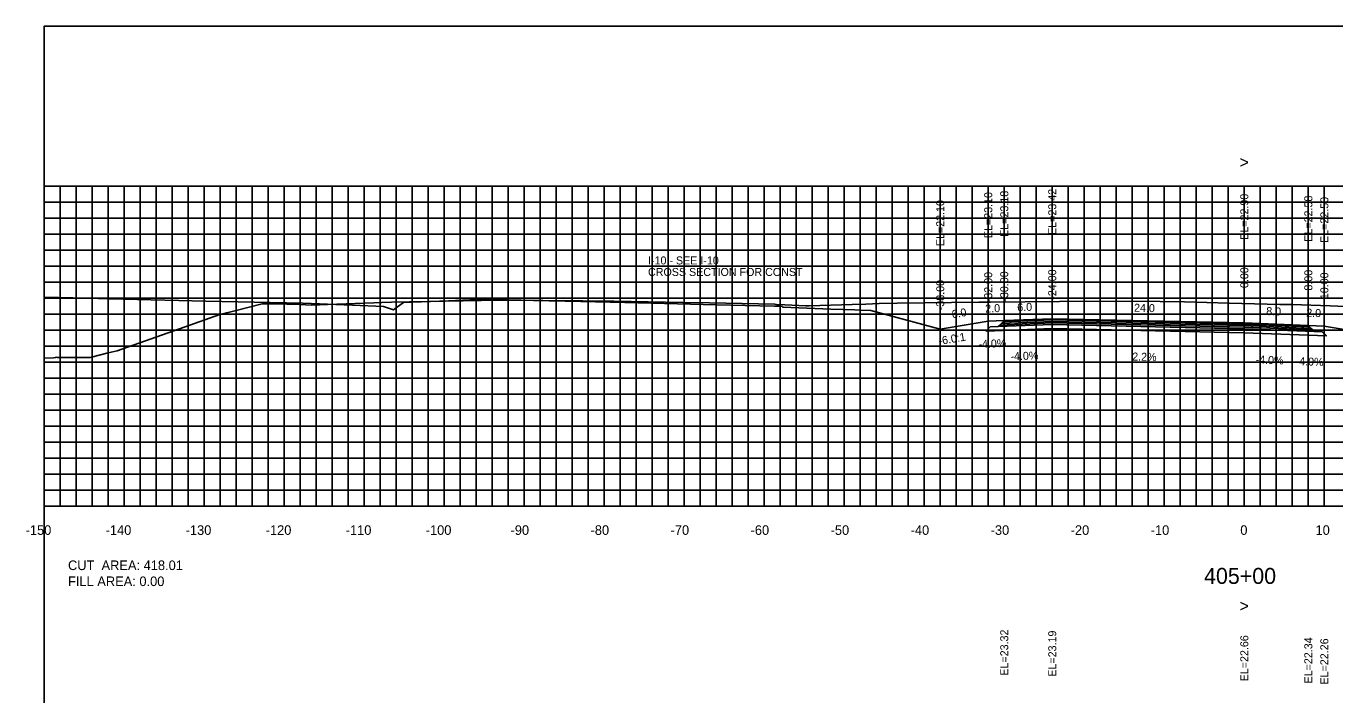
# Model space of a CAD drawing. Extents: x 1800976 to 1805104, y 250057 to 250580.
# Drawn here: x 1802478.8 to 1802642.3, y 250185.8 to 250269.4 of the extents above; entities that cross this region are included whole.
import ezdxf

# ---------------------------------------------------------------- set-up
doc = ezdxf.new("R2010")
doc.units = 0
for name, color, linetype in [('1', 7, 'Continuous'), ('10', 7, 'Continuous'), ('3', 7, 'Continuous'), ('4', 7, 'Continuous'), ('60', 7, 'Continuous'), ('ANNO-TXT', 7, 'Continuous'), ('BASE', 7, 'Continuous'), ('CL-CNST', 7, 'Continuous'), ('Level 62', 7, 'Continuous'), ('LOWER BINDER', 7, 'Continuous'), ('M-ROADS', 7, 'Continuous'), ('UPPER BINDER', 7, 'Continuous'), ('WEARING', 7, 'Continuous')]:
    doc.layers.add(name, color=color, linetype=linetype)

msp = doc.modelspace()

# ---------------------------------------------------------------- linework, layer by layer
for p, q in [((1802607, 250232.86), (1802607, 250234.86)), ((1802593, 250231.54), (1802593, 250233.54)), ((1802599, 250232.54), (1802599, 250234.54)), ((1802601, 250232.62), (1802601, 250234.62)), ((1802631, 250232.33), (1802631, 250234.33)), ((1802639, 250232.01), (1802639, 250234.01)), ((1802641, 250231.93), (1802641, 250233.93))]:
    msp.add_line(p, q)
msp.add_lwpolyline([(1802481, 250079.43), (1802781, 250079.43), (1802781, 250269.43), (1802481, 250269.43)], close=True)
at = {"layer": '60'}
for p, q in [((1802480.94, 250249.43), (1802481, 250249.43)), ((1802481, 250209.43), (1802481, 250249.43)), ((1802480.94, 250239.43), (1802481, 250239.43)), ((1802480.94, 250229.43), (1802481, 250229.43)), ((1802480.94, 250219.43), (1802481, 250219.43)), ((1802480.94, 250209.43), (1802481, 250209.43)), ((1802481, 250209.43), (1802781, 250209.43)), ((1802481, 250209.37), (1802481, 250209.43)), ((1802491, 250209.37), (1802491, 250209.43)), ((1802501, 250209.37), (1802501, 250209.43)), ((1802511, 250209.37), (1802511, 250209.43)), ((1802521, 250209.37), (1802521, 250209.43)), ((1802531, 250209.37), (1802531, 250209.43)), ((1802541, 250209.37), (1802541, 250209.43)), ((1802551, 250209.37), (1802551, 250209.43)), ((1802561, 250209.37), (1802561, 250209.43)), ((1802571, 250209.37), (1802571, 250209.43)), ((1802581, 250209.37), (1802581, 250209.43)), ((1802591, 250209.37), (1802591, 250209.43)), ((1802601, 250209.37), (1802601, 250209.43)), ((1802611, 250209.37), (1802611, 250209.43)), ((1802621, 250209.37), (1802621, 250209.43)), ((1802631, 250209.37), (1802631, 250209.43)), ((1802641, 250209.37), (1802641, 250209.43))]:
    msp.add_line(p, q, dxfattribs=at)
at = {"layer": 'BASE'}
msp.add_lwpolyline([(1802599.25, 250231.83), (1802600.25, 250231.87), (1802607, 250232.14), (1802631, 250231.61), (1802639.75, 250231.26), (1802640.75, 250231.22), (1802641.27, 250230.7), (1802631, 250231.11), (1802607, 250231.64), (1802598.73, 250231.3)], close=True, dxfattribs=at)
at = {"layer": 'CL-CNST'}
for points in [[(1802481, 250235.54), (1802486.39, 250235.41), (1802489.16, 250235.35), (1802497.83, 250235.15), (1802501.24, 250235.07), (1802509.28, 250234.88), (1802513.33, 250234.78), (1802519.54, 250234.53), (1802523.41, 250234.37), (1802523.92, 250234.21), (1802524.66, 250233.98), (1802525.18, 250234.35), (1802525.92, 250234.89), (1802531.56, 250235.11), (1802535.99, 250235.28), (1802542.15, 250235.14), (1802548.08, 250235), (1802553.58, 250234.87), (1802560.16, 250234.72), (1802565.01, 250234.6), (1802572.25, 250234.44), (1802572.89, 250234.41), (1802573.25, 250234.39), (1802573.28, 250234.37), (1802573.32, 250234.32), (1802579.33, 250234.07), (1802582.32, 250233.95), (1802582.95, 250233.92), (1802584.33, 250233.87), (1802593, 250231.54)], [(1802593, 250231.54), (1802599, 250232.54), (1802601, 250232.62), (1802607, 250232.86), (1802631, 250232.33), (1802639, 250232.01), (1802641, 250231.93), (1802671, 250226.93), (1802675, 250226.93), (1802697.32, 250232.51)]]:
    msp.add_lwpolyline(points, dxfattribs=at)
at = {"layer": 'Level 62'}
for p, q in [((1802481, 250249.43), (1802781, 250249.43)), ((1802481, 250209.43), (1802481, 250249.43)), ((1802483, 250209.43), (1802483, 250249.43)), ((1802485, 250209.43), (1802485, 250249.43)), ((1802487, 250209.43), (1802487, 250249.43)), ((1802489, 250209.43), (1802489, 250249.43)), ((1802491, 250209.43), (1802491, 250249.43)), ((1802493, 250209.43), (1802493, 250249.43)), ((1802495, 250209.43), (1802495, 250249.43)), ((1802497, 250209.43), (1802497, 250249.43)), ((1802499, 250209.43), (1802499, 250249.43)), ((1802501, 250209.43), (1802501, 250249.43)), ((1802503, 250209.43), (1802503, 250249.43)), ((1802505, 250209.43), (1802505, 250249.43)), ((1802507, 250209.43), (1802507, 250249.43)), ((1802509, 250209.43), (1802509, 250249.43)), ((1802511, 250209.43), (1802511, 250249.43)), ((1802513, 250209.43), (1802513, 250249.43)), ((1802515, 250209.43), (1802515, 250249.43)), ((1802517, 250209.43), (1802517, 250249.43)), ((1802519, 250209.43), (1802519, 250249.43)), ((1802521, 250209.43), (1802521, 250249.43)), ((1802523, 250209.43), (1802523, 250249.43)), ((1802525, 250209.43), (1802525, 250249.43)), ((1802527, 250209.43), (1802527, 250249.43)), ((1802529, 250209.43), (1802529, 250249.43)), ((1802531, 250209.43), (1802531, 250249.43)), ((1802533, 250209.43), (1802533, 250249.43)), ((1802535, 250209.43), (1802535, 250249.43)), ((1802537, 250209.43), (1802537, 250249.43)), ((1802539, 250209.43), (1802539, 250249.43)), ((1802541, 250209.43), (1802541, 250249.43)), ((1802543, 250209.43), (1802543, 250249.43)), ((1802545, 250209.43), (1802545, 250249.43)), ((1802547, 250209.43), (1802547, 250249.43)), ((1802549, 250209.43), (1802549, 250249.43)), ((1802551, 250209.43), (1802551, 250249.43)), ((1802553, 250209.43), (1802553, 250249.43)), ((1802555, 250209.43), (1802555, 250249.43)), ((1802557, 250209.43), (1802557, 250249.43)), ((1802559, 250209.43), (1802559, 250249.43)), ((1802561, 250209.43), (1802561, 250249.43)), ((1802563, 250209.43), (1802563, 250249.43)), ((1802565, 250209.43), (1802565, 250249.43)), ((1802567, 250209.43), (1802567, 250249.43)), ((1802569, 250209.43), (1802569, 250249.43)), ((1802571, 250209.43), (1802571, 250249.43)), ((1802573, 250209.43), (1802573, 250249.43)), ((1802575, 250209.43), (1802575, 250249.43)), ((1802577, 250209.43), (1802577, 250249.43)), ((1802579, 250209.43), (1802579, 250249.43)), ((1802581, 250209.43), (1802581, 250249.43)), ((1802583, 250209.43), (1802583, 250249.43)), ((1802585, 250209.43), (1802585, 250249.43)), ((1802587, 250209.43), (1802587, 250249.43)), ((1802589, 250209.43), (1802589, 250249.43)), ((1802591, 250209.43), (1802591, 250249.43)), ((1802593, 250209.43), (1802593, 250249.43)), ((1802595, 250209.43), (1802595, 250249.43)), ((1802597, 250209.43), (1802597, 250249.43)), ((1802599, 250209.43), (1802599, 250249.43)), ((1802601, 250209.43), (1802601, 250249.43)), ((1802603, 250209.43), (1802603, 250249.43)), ((1802605, 250209.43), (1802605, 250249.43)), ((1802607, 250209.43), (1802607, 250249.43)), ((1802609, 250209.43), (1802609, 250249.43)), ((1802611, 250209.43), (1802611, 250249.43)), ((1802613, 250209.43), (1802613, 250249.43)), ((1802615, 250209.43), (1802615, 250249.43)), ((1802617, 250209.43), (1802617, 250249.43)), ((1802619, 250209.43), (1802619, 250249.43)), ((1802621, 250209.43), (1802621, 250249.43)), ((1802623, 250209.43), (1802623, 250249.43)), ((1802625, 250209.43), (1802625, 250249.43)), ((1802627, 250209.43), (1802627, 250249.43)), ((1802629, 250209.43), (1802629, 250249.43)), ((1802631, 250209.43), (1802631, 250249.43)), ((1802633, 250209.43), (1802633, 250249.43)), ((1802635, 250209.43), (1802635, 250249.43)), ((1802637, 250209.43), (1802637, 250249.43)), ((1802639, 250209.43), (1802639, 250249.43)), ((1802641, 250209.43), (1802641, 250249.43)), ((1802481, 250247.43), (1802781, 250247.43)), ((1802481, 250245.43), (1802781, 250245.43)), ((1802481, 250243.43), (1802781, 250243.43)), ((1802481, 250241.43), (1802781, 250241.43)), ((1802481, 250239.43), (1802781, 250239.43)), ((1802481, 250237.43), (1802781, 250237.43)), ((1802481, 250235.43), (1802781, 250235.43)), ((1802481, 250233.43), (1802781, 250233.43)), ((1802481, 250231.43), (1802781, 250231.43)), ((1802481, 250229.43), (1802781, 250229.43)), ((1802481, 250227.43), (1802781, 250227.43)), ((1802481, 250225.43), (1802781, 250225.43)), ((1802481, 250223.43), (1802781, 250223.43)), ((1802481, 250221.43), (1802781, 250221.43)), ((1802481, 250219.43), (1802781, 250219.43)), ((1802481, 250217.43), (1802781, 250217.43)), ((1802481, 250215.43), (1802781, 250215.43)), ((1802481, 250213.43), (1802781, 250213.43)), ((1802481, 250211.43), (1802781, 250211.43)), ((1802481, 250209.43), (1802781, 250209.43))]:
    msp.add_line(p, q, dxfattribs=at)
at = {"layer": 'LOWER BINDER'}
for points in [[(1802607, 250232.33), (1802631, 250231.8), (1802639.55, 250231.46), (1802639.75, 250231.26), (1802631, 250231.61), (1802607, 250232.14), (1802600.25, 250231.87), (1802600.45, 250232.06)], [(1802607, 250232.52), (1802631, 250231.99), (1802639.36, 250231.65), (1802639.55, 250231.46), (1802631, 250231.8), (1802607, 250232.33), (1802600.45, 250232.06), (1802600.65, 250232.26)]]:
    msp.add_lwpolyline(points, close=True, dxfattribs=at)
at = {"layer": 'M-ROADS'}
msp.add_lwpolyline([(1802481, 250227.92), (1802482.17, 250227.98), (1802482.45, 250227.99), (1802482.55, 250228.03), (1802482.68, 250228.02), (1802483.04, 250228), (1802485.32, 250228), (1802486.76, 250228), (1802489.02, 250228.57), (1802490.15, 250228.86), (1802498.53, 250231.79), (1802502.96, 250233.39), (1802504.86, 250233.86), (1802508.28, 250234.7), (1802508.83, 250234.7), (1802509.69, 250234.7), (1802512.96, 250234.64), (1802514.45, 250234.57), (1802516.43, 250234.63), (1802522.21, 250234.85), (1802523.17, 250234.88), (1802523.22, 250234.88), (1802524.42, 250234.92), (1802535.62, 250235.15), (1802536.34, 250235.17), (1802538.37, 250235.16), (1802548.32, 250235.11), (1802552.2, 250235.04), (1802560.82, 250234.89), (1802564.18, 250234.83), (1802572.34, 250234.66), (1802572.52, 250234.65), (1802573.58, 250234.6), (1802576.2, 250234.48), (1802576.61, 250234.46), (1802582.01, 250234.64), (1802583.7, 250234.69), (1802585.35, 250234.74), (1802587.62, 250234.81), (1802597.84, 250234.93), (1802598.06, 250234.93), (1802598.07, 250234.93), (1802598.31, 250234.93), (1802599.25, 250234.93), (1802599.3, 250234.93), (1802607.92, 250235.01), (1802611.3, 250235.03), (1802620.49, 250234.99), (1802623.52, 250234.98), (1802629.11, 250234.82), (1802635.46, 250234.65), (1802635.58, 250234.65), (1802636.72, 250234.62), (1802636.79, 250234.62), (1802636.93, 250234.62), (1802641.74, 250234.45), (1802644.59, 250234.36)], dxfattribs=at)
at = {"layer": 'UPPER BINDER'}
msp.add_lwpolyline([(1802639.36, 250231.65), (1802639.16, 250231.85), (1802631, 250232.18), (1802607, 250232.71), (1802600.85, 250232.46), (1802600.65, 250232.26), (1802607, 250232.52), (1802631, 250231.99)], close=True, dxfattribs=at)
at = {"layer": 'WEARING'}
msp.add_lwpolyline([(1802639.16, 250231.85), (1802639, 250232.01), (1802631, 250232.33), (1802607, 250232.86), (1802601, 250232.62), (1802600.85, 250232.46), (1802607, 250232.71), (1802631, 250232.18)], close=True, dxfattribs=at)

# ---------------------------------------------------------------- texts
msp.add_text('-6.0:1', height=1, rotation=9.4623).set_placement((1802592.87, 250229.57))
at = {"layer": '1'}
msp.add_text('405+00', height=2, dxfattribs=at).set_placement((1802625.97, 250199.7))
at = {"layer": '10'}
for s, p in [('-150', (1802478.7, 250205.83)), ('-140', (1802488.7, 250205.83)), ('-130', (1802498.7, 250205.83)), ('-120', (1802508.7, 250205.83)), ('-110', (1802518.7, 250205.83)), ('-100', (1802528.7, 250205.83)), ('-90', (1802539.3, 250205.83)), ('-80', (1802549.3, 250205.83)), ('-70', (1802559.3, 250205.83)), ('-60', (1802569.3, 250205.83)), ('-50', (1802579.3, 250205.83)), ('-40', (1802589.3, 250205.83)), ('-30', (1802599.3, 250205.83)), ('-20', (1802609.3, 250205.83)), ('-10', (1802619.3, 250205.83)), ('0', (1802630.5, 250205.83)), ('10', (1802639.9, 250205.83))]:
    msp.add_text(s, height=1.2, dxfattribs=at).set_placement(p)
at = {"layer": '3'}
for s, p in [('EL=23.10', (1802599.5, 250242.93)), ('EL=23.18', (1802601.5, 250243.09)), ('EL=23.42', (1802607.5, 250243.33)), ('EL=22.90', (1802631.5, 250242.72)), ('EL=22.58', (1802639.5, 250242.48)), ('EL=22.50', (1802641.5, 250242.32)), ('EL=22.10', (1802593.5, 250241.93)), ('-32.00', (1802599.5, 250234.91)), ('-30.00', (1802601.5, 250234.99)), ('-24.00', (1802607.5, 250235.23)), ('0.00', (1802631.5, 250236.69)), ('8.00', (1802639.5, 250236.37)), ('10.00', (1802641.5, 250235.3)), ('-38.00', (1802593.5, 250233.91)), ('EL=23.32', (1802601.5, 250188.23)), ('EL=23.19', (1802607.5, 250188.1)), ('EL=22.66', (1802631.5, 250187.52)), ('EL=22.34', (1802639.5, 250187.25)), ('EL=22.26', (1802641.5, 250187.12))]:
    msp.add_text(s, height=1, rotation=90, dxfattribs=at).set_placement(p)
for s, p in [('I-10 - SEE I-10 ', (1802556.48, 250239.64)), ('CROSS SECTION FOR CONST ', (1802556.48, 250238.2))]:
    msp.add_text(s, height=1, dxfattribs=at).set_placement(p)
at = {"layer": '4'}
for s, rotation, p in [('6.0', 2.2906, (1802602.64, 250233.78)), ('6.0', 9.4623, (1802594.52, 250232.9)), ('2.0', 2.2906, (1802598.64, 250233.62)), ('24.0', 358.7397, (1802617.21, 250233.73)), ('8.0', 357.7094, (1802633.72, 250233.32)), ('2.0', 357.7094, (1802638.72, 250233.12)), ('-4.0%', 2.2906, (1802597.79, 250229.18)), ('-4.0%', 2.2906, (1802601.79, 250227.64)), ('2.2%', 358.7397, (1802616.98, 250227.63)), ('-4.0%', 357.7094, (1802632.39, 250227.27)), ('-4.0%', 357.7094, (1802637.39, 250227.07))]:
    msp.add_text(s, height=1, rotation=rotation, dxfattribs=at).set_placement(p)
at = {"layer": '60'}
for s, height, p in [('>', 1.5, (1802630.39, 250251.68)), ('-', 0.0001, (1802481, 250209.43)), ('>', 1.5, (1802630.39, 250196.21))]:
    msp.add_text(s, height=height, dxfattribs=at).set_placement(p)
at = {"layer": 'ANNO-TXT'}
for s, p in [('CUT  AREA: 418.01', (1802484, 250201.43)), ('FILL AREA: 0.00', (1802484, 250199.43))]:
    msp.add_text(s, height=1.2, dxfattribs=at).set_placement(p)

doc.saveas('drawing.dxf')
